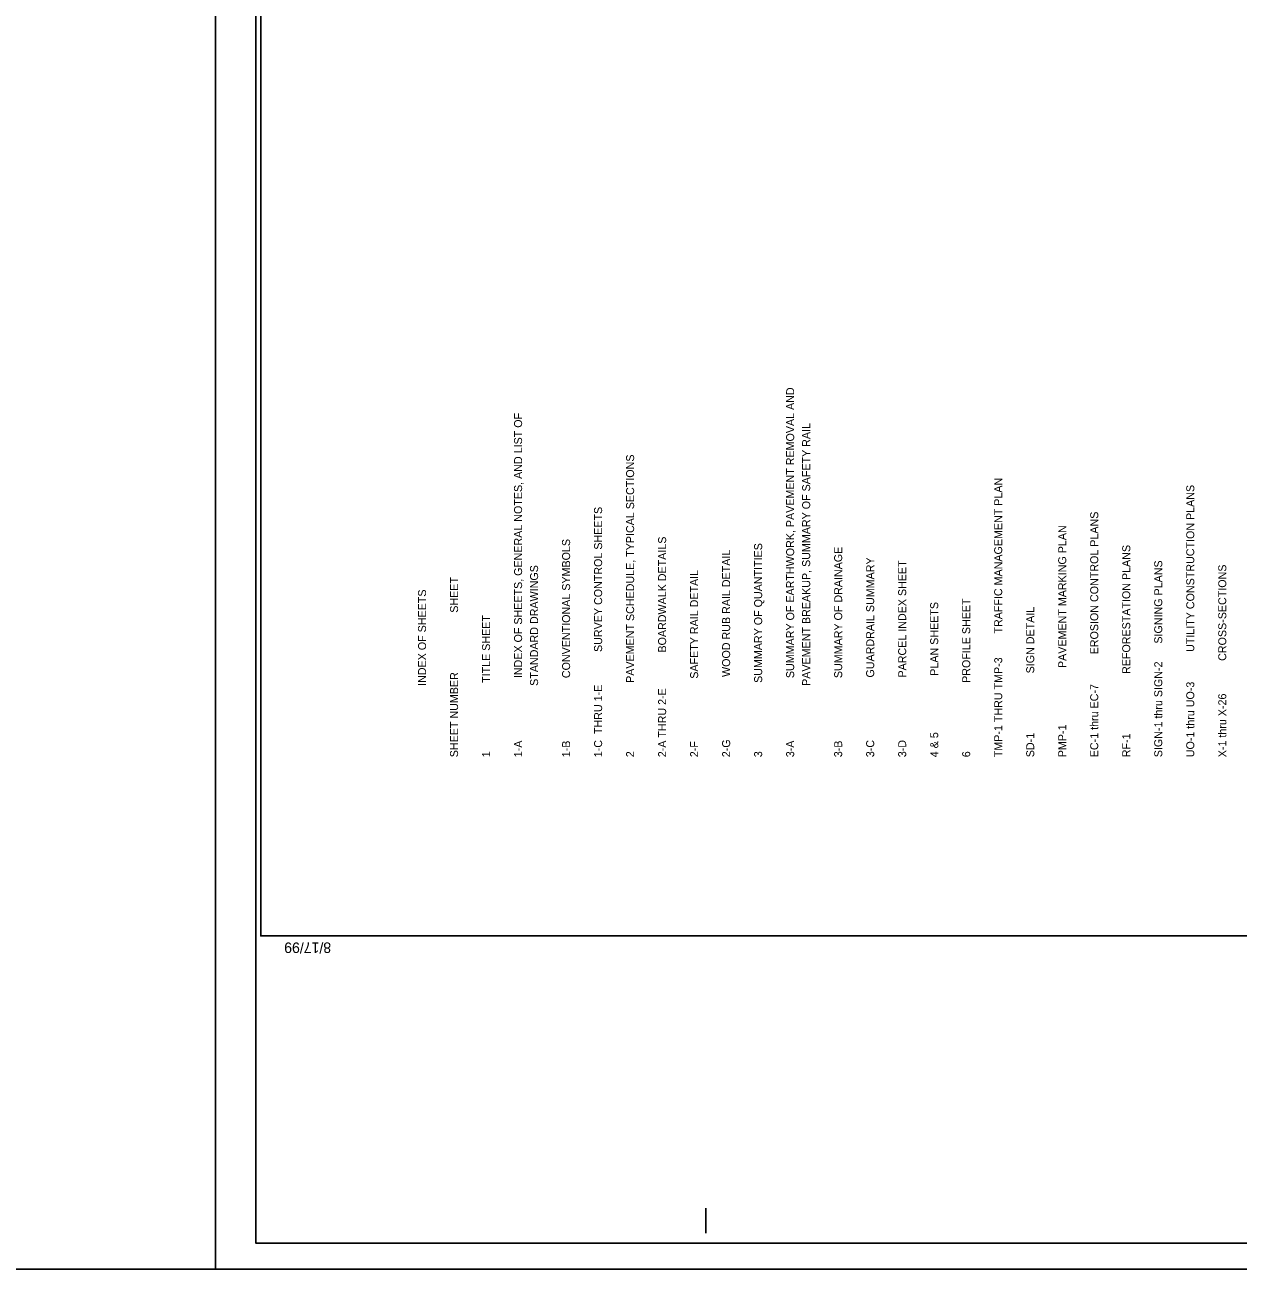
# Model space of a CAD drawing. Extents: x 2026893 to 2039781, y 729195 to 739590.
# Drawn here: x 2030909 to 2033032, y 733696 to 735872 of the extents above; entities that cross this region are included whole.
import ezdxf

# ---------------------------------------------------------------- set-up
doc = ezdxf.new("R2010")
doc.units = 0
for name, color, linetype in [('Old_Level_1', 7, 'Continuous'), ('Scratch_Level_3', 7, 'Continuous'), ('Sheet Cutting Line CELL', 7, 'Continuous'), ('Sheet Plan CELL', 7, 'Continuous'), ('Sheet Plot Border Inside CELL', 7, 'Continuous'), ('Sheet Plot Border Outside CELL', 7, 'Continuous')]:
    doc.layers.add(name, color=color, linetype=linetype)

msp = doc.modelspace()

# ---------------------------------------------------------------- linework, layer by layer
at = {"layer": 'Scratch_Level_3'}
msp.add_line((2031242.8, 733695.9), (2030742.8, 733695.9), dxfattribs=at)
at = {"layer": 'Sheet Cutting Line CELL'}
for p, q in [((2031242.8, 739588.2), (2031242.8, 733695.9)), ((2031242.8, 733695.9), (2035075.3, 733695.9))]:
    msp.add_line(p, q, dxfattribs=at)
at = {"layer": 'Sheet Plan CELL'}
for p, q in [((2031321.6, 734278.7), (2031321.6, 734278.7)), ((2032100.3, 733758.9), (2032100.3, 733802.7))]:
    msp.add_line(p, q, dxfattribs=at)
msp.add_lwpolyline([(2031321.6, 739528.7), (2031321.6, 734278.7), (2034996.6, 734278.7), (2034996.6, 739528.7)], close=True, dxfattribs=at)
at = {"layer": 'Sheet Plot Border Inside CELL'}
msp.add_lwpolyline([(2035005.3, 733741.4), (2035005.3, 739572.4), (2031312.8, 739572.4), (2031312.8, 733741.4)], close=True, dxfattribs=at)
at = {"layer": 'Sheet Plot Border Outside CELL'}
msp.add_lwpolyline([(2035075.3, 733695.9), (2035075.3, 739588.2), (2031242.8, 739588.2), (2031242.8, 733695.9)], close=True, dxfattribs=at)

# ---------------------------------------------------------------- texts
at = {"layer": 'Old_Level_1'}
for s, p in [('3-A                     SUMMARY OF EARTHWORK, PAVEMENT REMOVAL AND', (2032254.9, 734591.4)), ('1-A                     INDEX OF SHEETS, GENERAL NOTES, AND LIST OF ', (2031778.9, 734591.4)), ('                        PAVEMENT BREAKUP, SUMMARY OF SAFETY RAIL', (2032282.9, 734591.4)), ('2                       PAVEMENT SCHEDULE, TYPICAL SECTIONS', (2031974.9, 734591.4)), ('TMP-1 THRU TMP-3        TRAFFIC MANAGEMENT PLAN', (2032618.9, 734591.4)), ('UO-1 thru UO-3          UTILITY CONSTRUCTION PLANS', (2032954.9, 734591.4)), ('1-C  THRU 1-E           SURVEY CONTROL SHEETS', (2031918.9, 734591.4)), ('EC-1 thru EC-7          EROSION CONTROL PLANS', (2032786.9, 734591.4)), ('PMP-1                   PAVEMENT MARKING PLAN', (2032730.9, 734591.4)), ('1-B                     CONVENTIONAL SYMBOLS', (2031862.9, 734591.4)), ('2-A THRU 2-E            BOARDWALK DETAILS', (2032030.9, 734591.4)), ('3                       SUMMARY OF QUANTITIES ', (2032198.9, 734591.4)), ('3-B                     SUMMARY OF DRAINAGE', (2032338.9, 734591.4)), ('RF-1                    REFORESTATION PLANS', (2032842.9, 734591.4)), ('2-G                     WOOD RUB RAIL DETAIL', (2032142.9, 734591.4)), ('3-C                     GUARDRAIL SUMMARY ', (2032394.9, 734591.4)), ('                        STANDARD DRAWINGS', (2031806.9, 734591.4)), ('2-F                     SAFETY RAIL DETAIL', (2032086.9, 734591.4)), ('3-D                     PARCEL INDEX SHEET ', (2032450.9, 734591.4)), ('SIGN-1 thru SIGN-2      SIGNING PLANS', (2032898.9, 734591.4)), ('X-1 thru X-26           CROSS-SECTIONS', (2033010.9, 734591.4)), ('SHEET NUMBER                    SHEET   ', (2031666.9, 734591.4)), ('                        INDEX OF SHEETS ', (2031610.9, 734591.4)), ('4 & 5                   PLAN SHEETS', (2032506.9, 734591.4)), ('6                       PROFILE SHEET  ', (2032562.9, 734591.4)), ('SD-1                    SIGN DETAIL', (2032674.9, 734591.4)), ('1                       TITLE SHEET', (2031722.9, 734591.4))]:
    msp.add_text(s, height=14, rotation=90, dxfattribs=at).set_placement(p)
at = {"layer": 'Sheet Plan CELL'}
msp.add_text('8/17/99', height=18.38, rotation=180, dxfattribs=at).set_placement((2031444.8, 734267.3))

doc.saveas('drawing.dxf')
